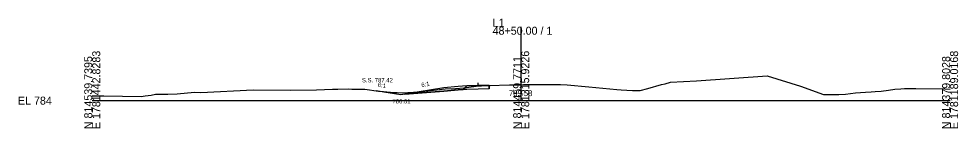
# Model space of a CAD drawing. Extents: x 5574 to 10203, y -10 to 9546.
# Drawn here: x 5574.3 to 5902.8, y 5490.3 to 5528.7 of the extents above; entities that cross this region are included whole.
import ezdxf

# ---------------------------------------------------------------- set-up
doc = ezdxf.new("R2010")
doc.units = 0
for name, color, linetype in [('Exist Cross Section Cell', 7, 'Continuous'), ('Exist XS Center Line Elevation Label', 7, 'Continuous'), ('Exist XS Ground Line', 7, 'Continuous'), ('Prop XS Ditch Slope Text', 7, 'Continuous'), ('Prop XS Ditch Standard Text', 7, 'Continuous'), ('Prop XS Dump Level', 7, 'Continuous'), ('Prop XS Earthwork Shape', 7, 'Continuous'), ('Prop XS EOT Tick Mark', 7, 'Continuous'), ('Prop XS Finish Grade', 7, 'Continuous'), ('Prop XS Finish Grade Earthwork', 7, 'Continuous'), ('Prop XS Finish Grade Paved Shoulder', 7, 'Continuous'), ('Prop XS Finish Grade Pavement', 7, 'Continuous'), ('Prop XS Hydro Typical Ditch Data', 7, 'Continuous'), ('Prop XS Pvmt Edge Slope', 7, 'Continuous'), ('Prop XS Side Slope Text', 7, 'Continuous'), ('Prop XS SS Elevation Text', 7, 'Continuous'), ('Prop XS Subgrade Earthwork', 7, 'Continuous'), ('Scratch_Level_3', 7, 'Continuous'), ('Scratch_Level_6', 7, 'Continuous')]:
    doc.layers.add(name, color=color, linetype=linetype)

msp = doc.modelspace()

# ---------------------------------------------------------------- linework, layer by layer
at = {"layer": 'Exist Cross Section Cell'}
for p, q in [((5750, 5500), (5750, 5525.91)), ((5600, 5500), (5750, 5500)), ((5750, 5500), (5900, 5500))]:
    msp.add_line(p, q, dxfattribs=at)
at = {"layer": 'Exist XS Ground Line'}
for p, q in [((5800.36, 5505.93), (5802.17, 5506.48)), ((5802.17, 5506.48), (5811.37, 5506.92)), ((5811.37, 5506.92), (5835.99, 5508.64)), ((5835.99, 5508.64), (5847.71, 5505.04)), ((5629.7, 5502.42), (5635.71, 5502.94)), ((5635.71, 5502.94), (5638, 5502.8)), ((5638, 5502.8), (5656.33, 5503.78)), ((5656.33, 5503.78), (5669.37, 5503.61)), ((5669.37, 5503.61), (5678.44, 5503.84)), ((5678.44, 5503.84), (5684.05, 5504.07)), ((5684.05, 5504.07), (5685.84, 5504.07)), ((5685.84, 5504.07), (5689.69, 5504.09)), ((5689.69, 5504.09), (5690.81, 5504.06)), ((5690.81, 5504.06), (5695.32, 5504.02)), ((5695.32, 5504.02), (5700.11, 5503.33)), ((5700.11, 5503.33), (5701.82, 5503.2)), ((5701.82, 5503.2), (5705.44, 5502.89)), ((5708.34, 5502.72), (5712.33, 5502.94)), ((5712.33, 5502.94), (5714.45, 5503.12)), ((5714.45, 5503.12), (5716.32, 5503.33)), ((5716.32, 5503.33), (5723.37, 5504.11)), ((5723.37, 5504.11), (5727.08, 5504.28)), ((5727.08, 5504.28), (5729.89, 5504.49)), ((5729.89, 5504.49), (5734.28, 5505.09)), ((5734.28, 5505.09), (5736.16, 5505.18)), ((5736.16, 5505.18), (5738.8, 5505.33)), ((5738.8, 5505.33), (5745.89, 5505.49)), ((5745.89, 5505.49), (5750, 5505.58)), ((5750, 5505.58), (5750.81, 5505.6)), ((5750.81, 5505.6), (5755.4, 5505.65)), ((5755.4, 5505.65), (5762.05, 5505.71)), ((5762.05, 5505.71), (5763.71, 5505.64)), ((5763.71, 5505.64), (5766.06, 5505.54)), ((5766.06, 5505.54), (5773.69, 5504.81)), ((5773.69, 5504.81), (5783.46, 5503.9)), ((5783.46, 5503.9), (5784.99, 5503.81)), ((5784.99, 5503.81), (5788.94, 5503.6)), ((5788.94, 5503.6), (5791.08, 5503.53)), ((5791.08, 5503.53), (5791.66, 5503.53)), ((5791.66, 5503.53), (5794.35, 5504.24)), ((5794.35, 5504.24), (5799.02, 5505.62)), ((5799.02, 5505.62), (5800.36, 5505.93)), ((5847.71, 5505.04), (5855.77, 5502.19)), ((5866.91, 5502.78), (5870.43, 5502.99)), ((5870.43, 5502.99), (5872.43, 5503.13)), ((5872.43, 5503.13), (5873.78, 5503.19)), ((5873.78, 5503.19), (5875.92, 5503.28)), ((5875.92, 5503.28), (5878.47, 5503.66)), ((5878.47, 5503.66), (5880.62, 5504.02)), ((5880.62, 5504.02), (5882.72, 5504.14)), ((5882.72, 5504.14), (5884.06, 5504.21)), ((5884.06, 5504.21), (5886.05, 5504.29)), ((5886.05, 5504.29), (5886.53, 5504.3)), ((5886.53, 5504.3), (5888.01, 5504.28)), ((5888.01, 5504.28), (5898.13, 5504.11)), ((5898.13, 5504.11), (5900, 5504.07)), ((5600, 5501.66), (5604.02, 5501.66)), ((5604.02, 5501.66), (5617.07, 5501.45)), ((5617.07, 5501.45), (5618.54, 5501.65)), ((5618.54, 5501.65), (5620.64, 5501.97)), ((5620.64, 5501.97), (5622.12, 5502.22)), ((5622.12, 5502.22), (5626.45, 5502.29)), ((5626.45, 5502.29), (5629.7, 5502.42)), ((5705.44, 5502.89), (5706.04, 5502.82)), ((5706.04, 5502.82), (5706.69, 5502.82)), ((5706.69, 5502.82), (5708.34, 5502.72)), ((5855.77, 5502.19), (5857.03, 5502.1)), ((5857.03, 5502.1), (5859.32, 5502.14)), ((5859.32, 5502.14), (5861.14, 5502.11)), ((5861.14, 5502.11), (5863.38, 5502.31)), ((5863.38, 5502.31), (5866.91, 5502.78))]:
    msp.add_line(p, q, dxfattribs=at)
at = {"layer": 'Prop XS Dump Level'}
msp.add_line((5738.8, 5505.36), (5734.96, 5505.28), dxfattribs=at)
msp.add_line((5738.8, 5505.36), (5734.96, 5505.28), dxfattribs=at)
at = {"layer": 'Prop XS Earthwork Shape'}
msp.add_lwpolyline([(5699.46, 5503.42), (5700.11, 5503.33), (5701.82, 5503.2), (5705.44, 5502.89), (5706.04, 5502.82), (5706.69, 5502.82), (5708.34, 5502.72), (5712.33, 5502.94), (5714.45, 5503.12), (5716.32, 5503.33), (5723.37, 5504.11), (5727.08, 5504.28), (5729.89, 5504.49), (5734.28, 5505.09), (5736.16, 5505.18), (5738.8, 5505.33), (5738.8, 5504.08), (5734.96, 5503.99), (5730.96, 5503.9), (5729.68, 5503.87), (5727.96, 5503.73), (5722.96, 5503.33), (5709.37, 5502.24), (5707.96, 5502.01), (5701.96, 5503.01)], close=True, dxfattribs=at)
at = {"layer": 'Prop XS EOT Tick Mark'}
msp.add_line((5734.96, 5505.24), (5734.96, 5506.24), dxfattribs=at)
at = {"layer": 'Prop XS Finish Grade'}
for p, q in [((5722.96, 5504.51), (5709.37, 5502.24)), ((5727.96, 5504.91), (5722.96, 5504.51)), ((5730.96, 5505.15), (5727.96, 5504.91))]:
    msp.add_line(p, q, dxfattribs=at)
at = {"layer": 'Prop XS Finish Grade Earthwork'}
for p, q in [((5701.96, 5503.01), (5699.46, 5503.42)), ((5707.96, 5502.01), (5701.96, 5503.01)), ((5709.37, 5502.24), (5707.96, 5502.01))]:
    msp.add_line(p, q, dxfattribs=at)
at = {"layer": 'Prop XS Finish Grade Paved Shoulder'}
msp.add_line((5734.96, 5505.24), (5730.96, 5505.15), dxfattribs=at)
at = {"layer": 'Prop XS Finish Grade Pavement'}
msp.add_line((5738.8, 5505.33), (5734.96, 5505.24), dxfattribs=at)
at = {"layer": 'Prop XS Hydro Typical Ditch Data'}
for p, q in [((5701.96, 5503.01), (5699.46, 5503.42)), ((5707.96, 5502.01), (5701.96, 5503.01)), ((5722.96, 5504.51), (5707.96, 5502.01))]:
    msp.add_line(p, q, dxfattribs=at)
at = {"layer": 'Prop XS Pvmt Edge Slope'}
msp.add_line((5730.96, 5505.15), (5729.68, 5503.87), dxfattribs=at)
at = {"layer": 'Prop XS Subgrade Earthwork'}
for p, q in [((5722.96, 5503.33), (5709.37, 5502.24)), ((5727.96, 5503.73), (5722.96, 5503.33)), ((5729.68, 5503.87), (5727.96, 5503.73)), ((5730.96, 5503.9), (5729.68, 5503.87)), ((5734.96, 5503.99), (5730.96, 5503.9)), ((5738.8, 5504.08), (5734.96, 5503.99)), ((5738.8, 5504.08), (5738.8, 5505.33))]:
    msp.add_line(p, q, dxfattribs=at)
at = {"layer": 'Scratch_Level_3'}
for p, q in [((5722.96, 5504.51), (5709.37, 5502.24)), ((5709.37, 5502.24), (5722.96, 5503.33)), ((5727.96, 5504.91), (5722.96, 5504.51)), ((5722.96, 5503.33), (5727.96, 5503.73)), ((5730.96, 5505.15), (5727.96, 5504.91)), ((5727.96, 5503.73), (5729.68, 5503.87)), ((5729.68, 5503.87), (5730.96, 5505.15))]:
    msp.add_line(p, q, dxfattribs=at)
at = {"layer": 'Scratch_Level_6'}
msp.add_lwpolyline([(5715.05, 5503.19), (5716.32, 5503.33), (5723.37, 5504.11), (5727.08, 5504.28), (5729.89, 5504.49), (5734.28, 5505.09), (5736.16, 5505.18), (5738.8, 5505.33), (5738.8, 5504.08), (5734.96, 5503.99), (5730.96, 5503.9), (5729.68, 5503.87), (5727.96, 5503.73), (5722.96, 5503.33), (5709.37, 5502.24)], close=True, dxfattribs=at)

# ---------------------------------------------------------------- texts
at = {"layer": 'Exist Cross Section Cell'}
for s, p in [('48+50.00 / 1', (5740, 5523.11)), ('L1', (5740, 5525.91)), ('EL 784', (5574, 5498.6))]:
    msp.add_text(s, height=2.8, dxfattribs=at).set_placement(p)
for s, p in [('E 1781442.8283', (5602.8, 5490)), ('E 1781315.9226', (5752.8, 5490)), ('E 1781189.0168', (5902.8, 5490)), ('N 814539.7395', (5600, 5490)), ('N 814459.7711', (5750, 5490)), ('N 814379.8028', (5900, 5490))]:
    msp.add_text(s, height=2.8, rotation=90, dxfattribs=at).set_placement(p)
at = {"layer": 'Exist XS Center Line Elevation Label'}
msp.add_text('789.58', height=2, dxfattribs=at).set_placement((5745.73, 5501.58))
at = {"layer": 'Prop XS Ditch Slope Text'}
msp.add_text('6:1', height=1.5, rotation=9.4623, dxfattribs=at).set_placement((5715.21, 5504.73))
at = {"layer": 'Prop XS Ditch Standard Text'}
msp.add_text('786.01', height=1.5, dxfattribs=at).set_placement((5704.99, 5499.01))
at = {"layer": 'Prop XS Dump Level'}
for s, height, p in [('Case4', 0.04, (5722.96, 5504.47)), ('Eop', 0.3, (5738.8, 5505.03))]:
    msp.add_text(s, height=height, dxfattribs=at).set_placement(p)
at = {"layer": 'Prop XS Side Slope Text'}
msp.add_text('6:1', height=1.5, rotation=350.5377, dxfattribs=at).set_placement((5699.76, 5504.89))
at = {"layer": 'Prop XS SS Elevation Text'}
msp.add_text('S.S. 787.42', height=1.5, dxfattribs=at).set_placement((5694.31, 5506.42))

doc.saveas('drawing.dxf')
